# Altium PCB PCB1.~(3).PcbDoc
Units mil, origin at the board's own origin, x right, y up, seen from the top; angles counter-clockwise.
Board outline 2756 x 2756 mil, 4 copper layers (Top Layer, Internal Plane 1, Internal Plane 2, Bottom Layer), stack 18.2 mil thick; 11 components, 12 nets, 54 pads, 0 vias.
Unrouted connection lines stored in the file: 36.
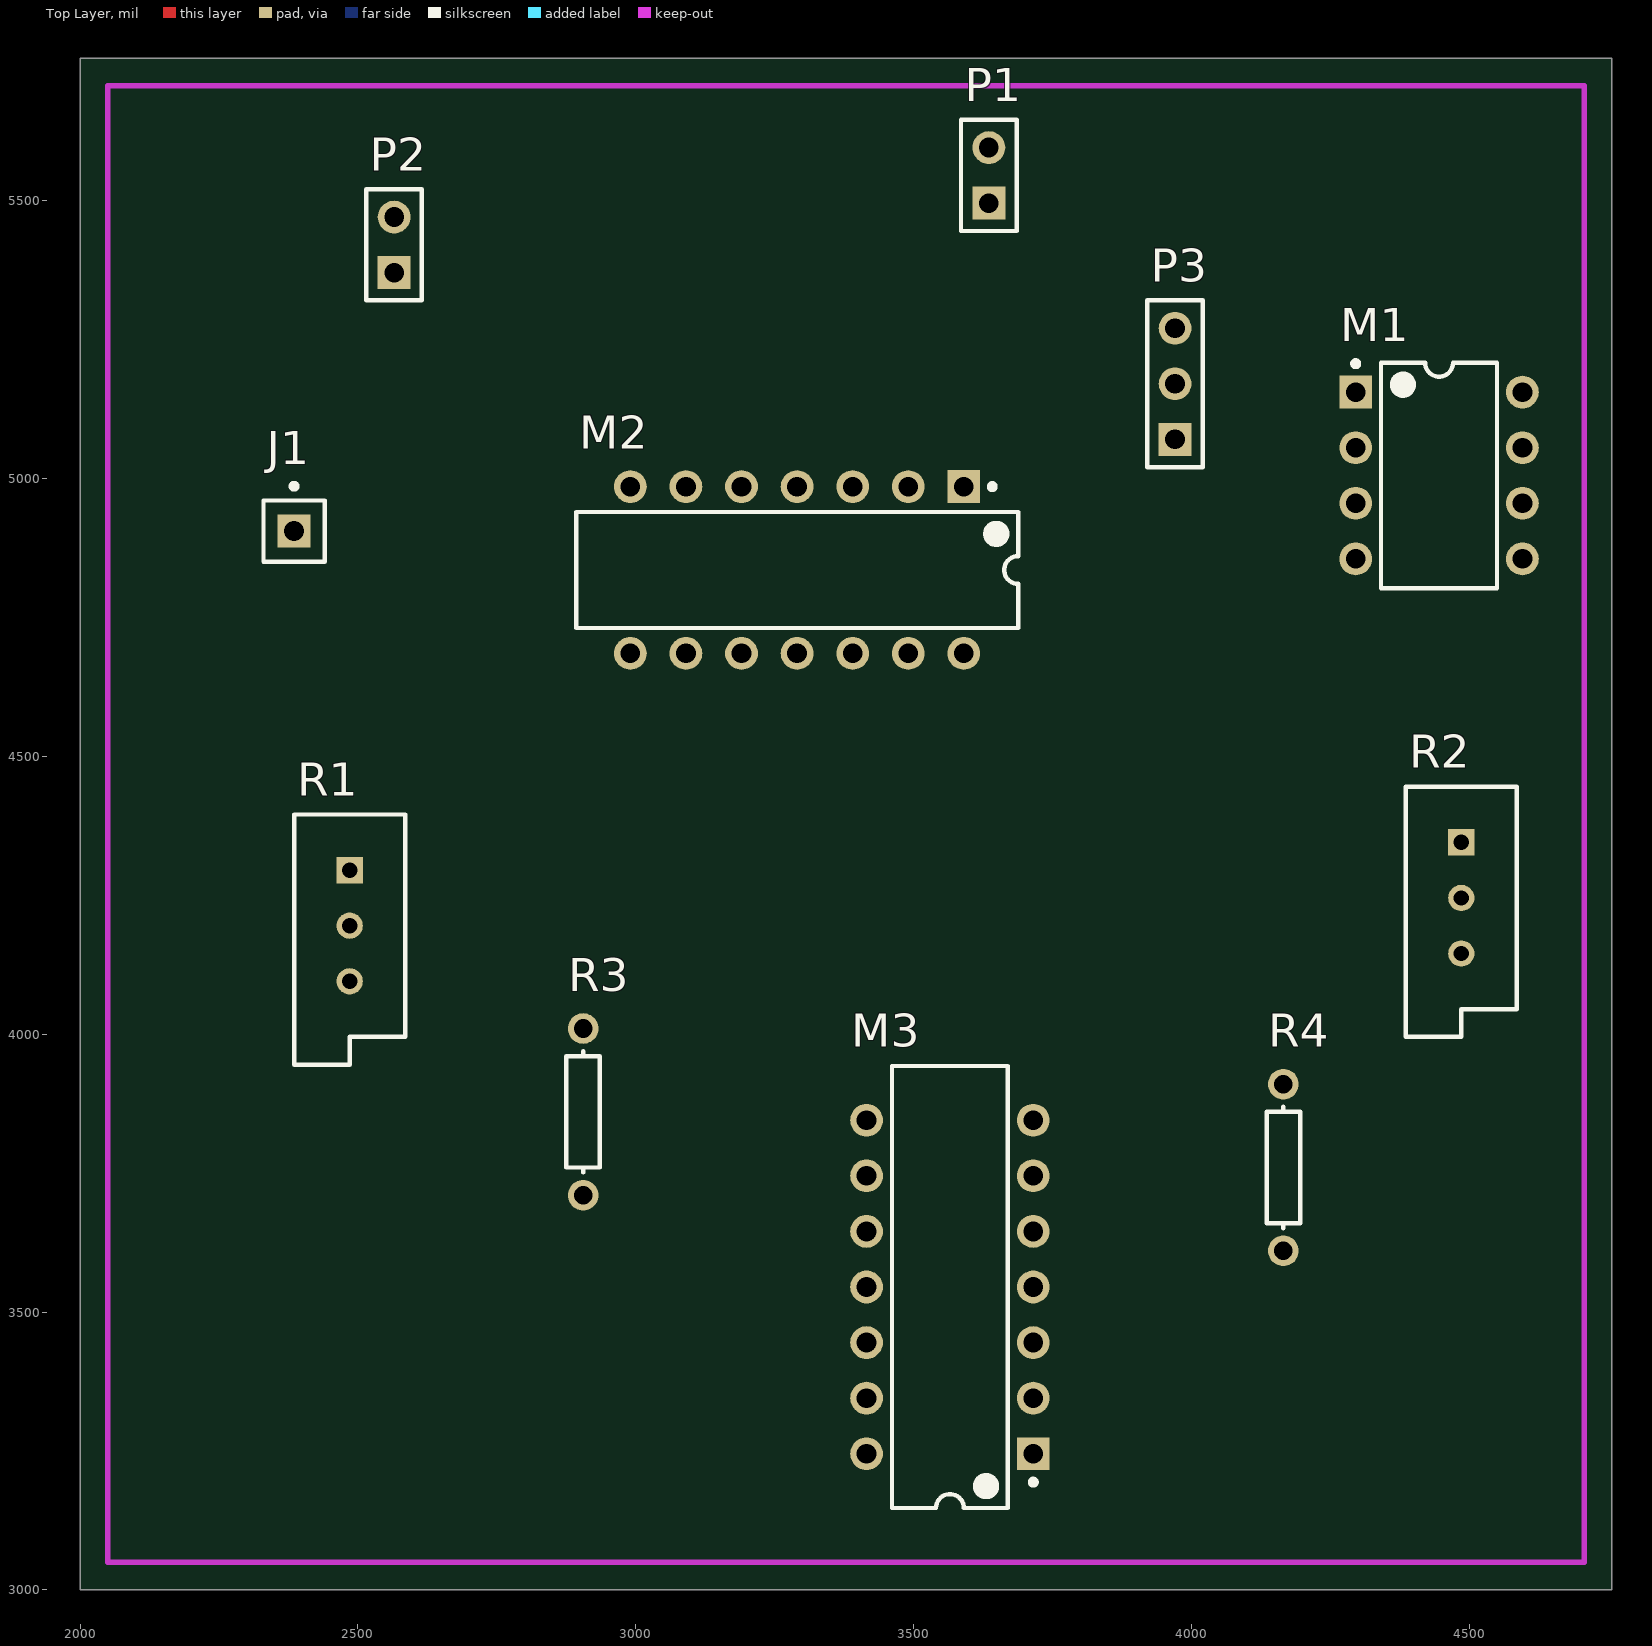
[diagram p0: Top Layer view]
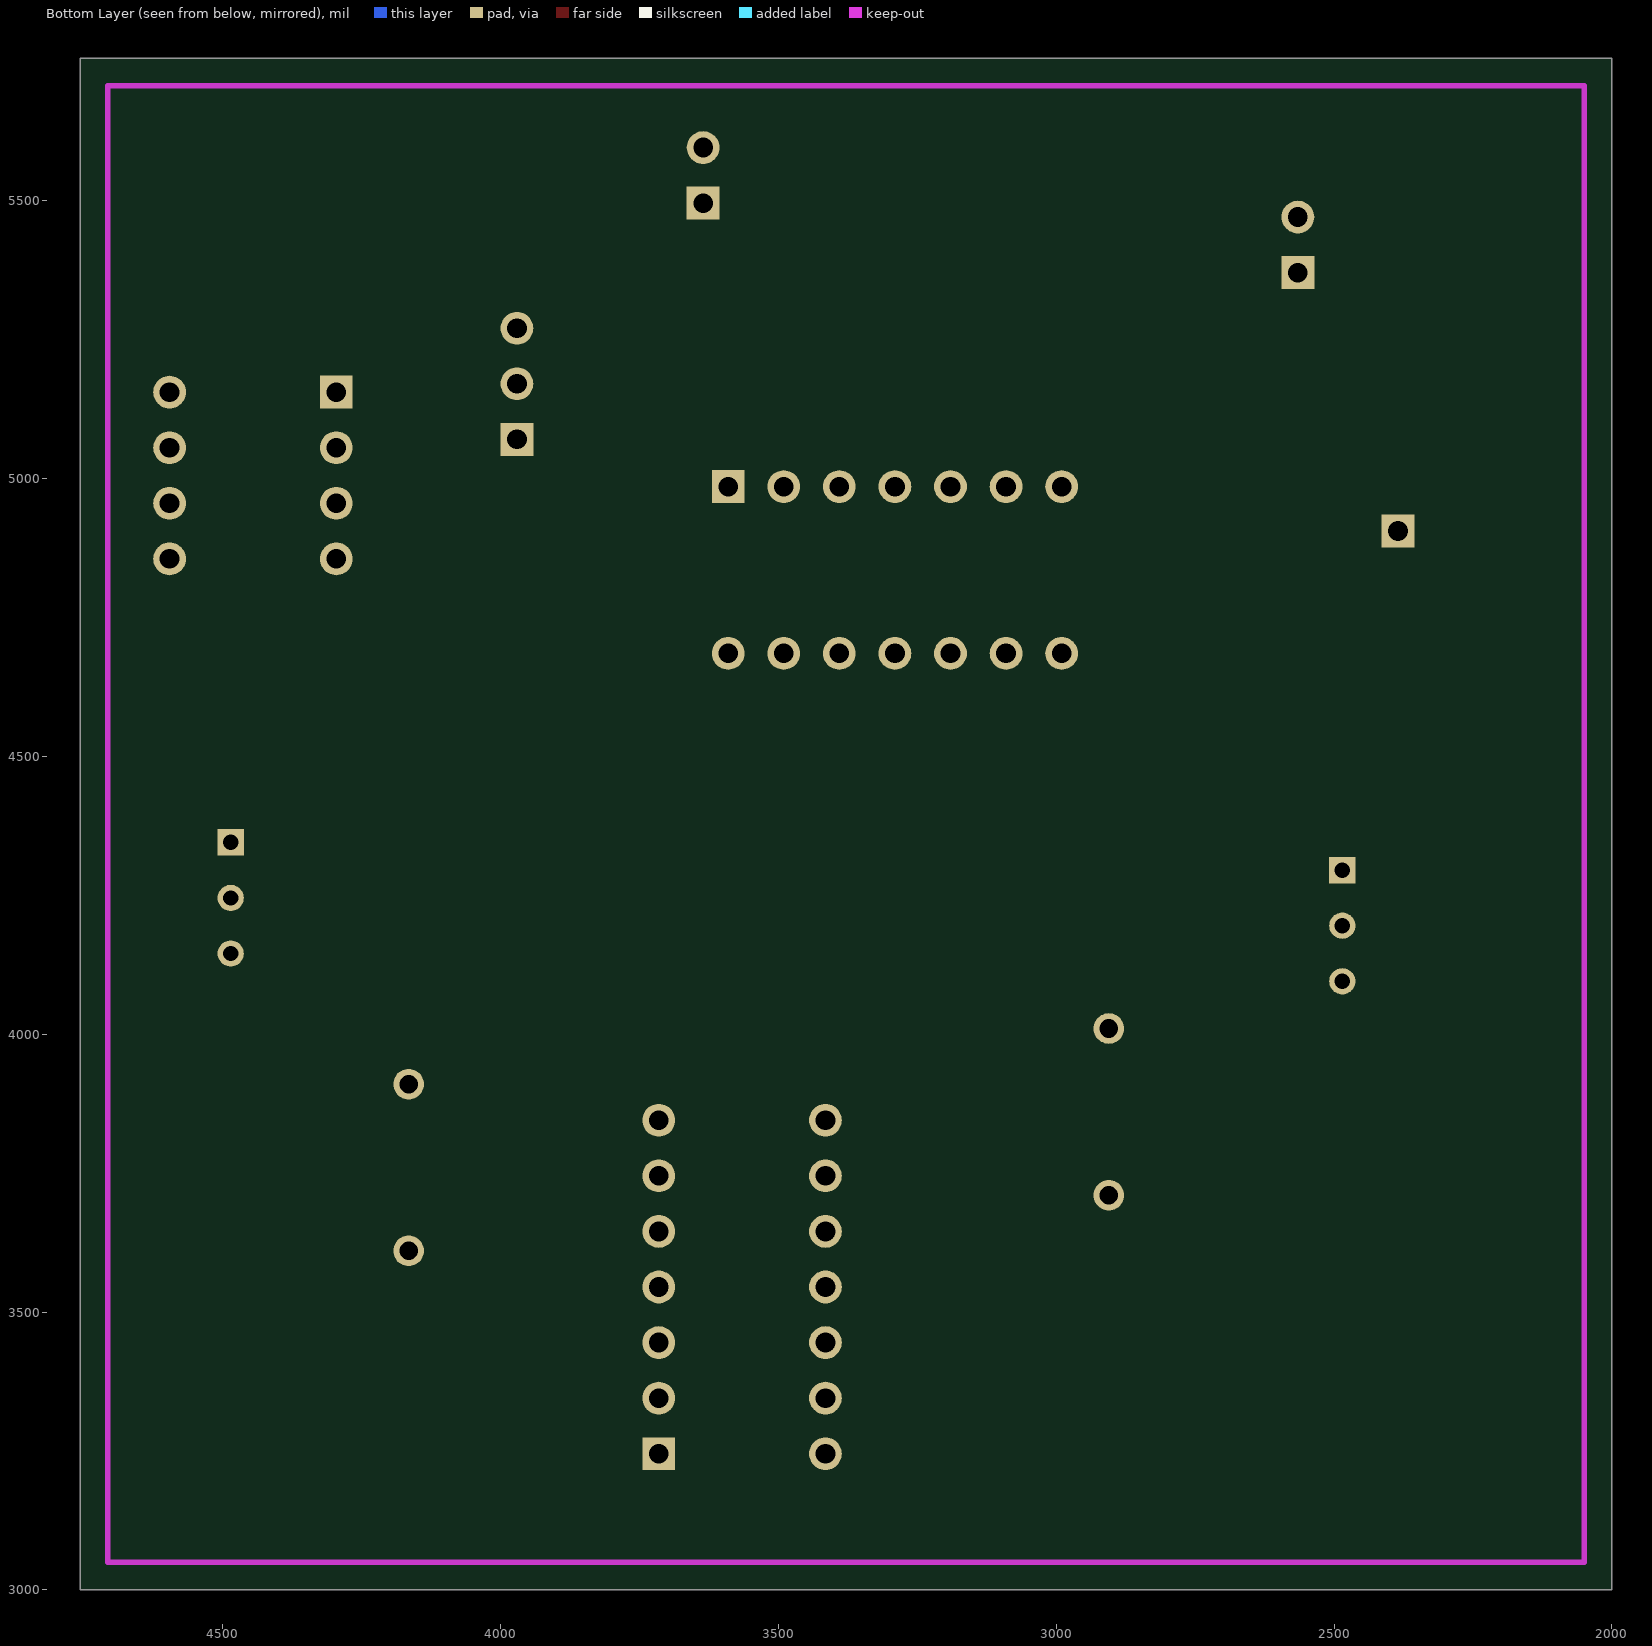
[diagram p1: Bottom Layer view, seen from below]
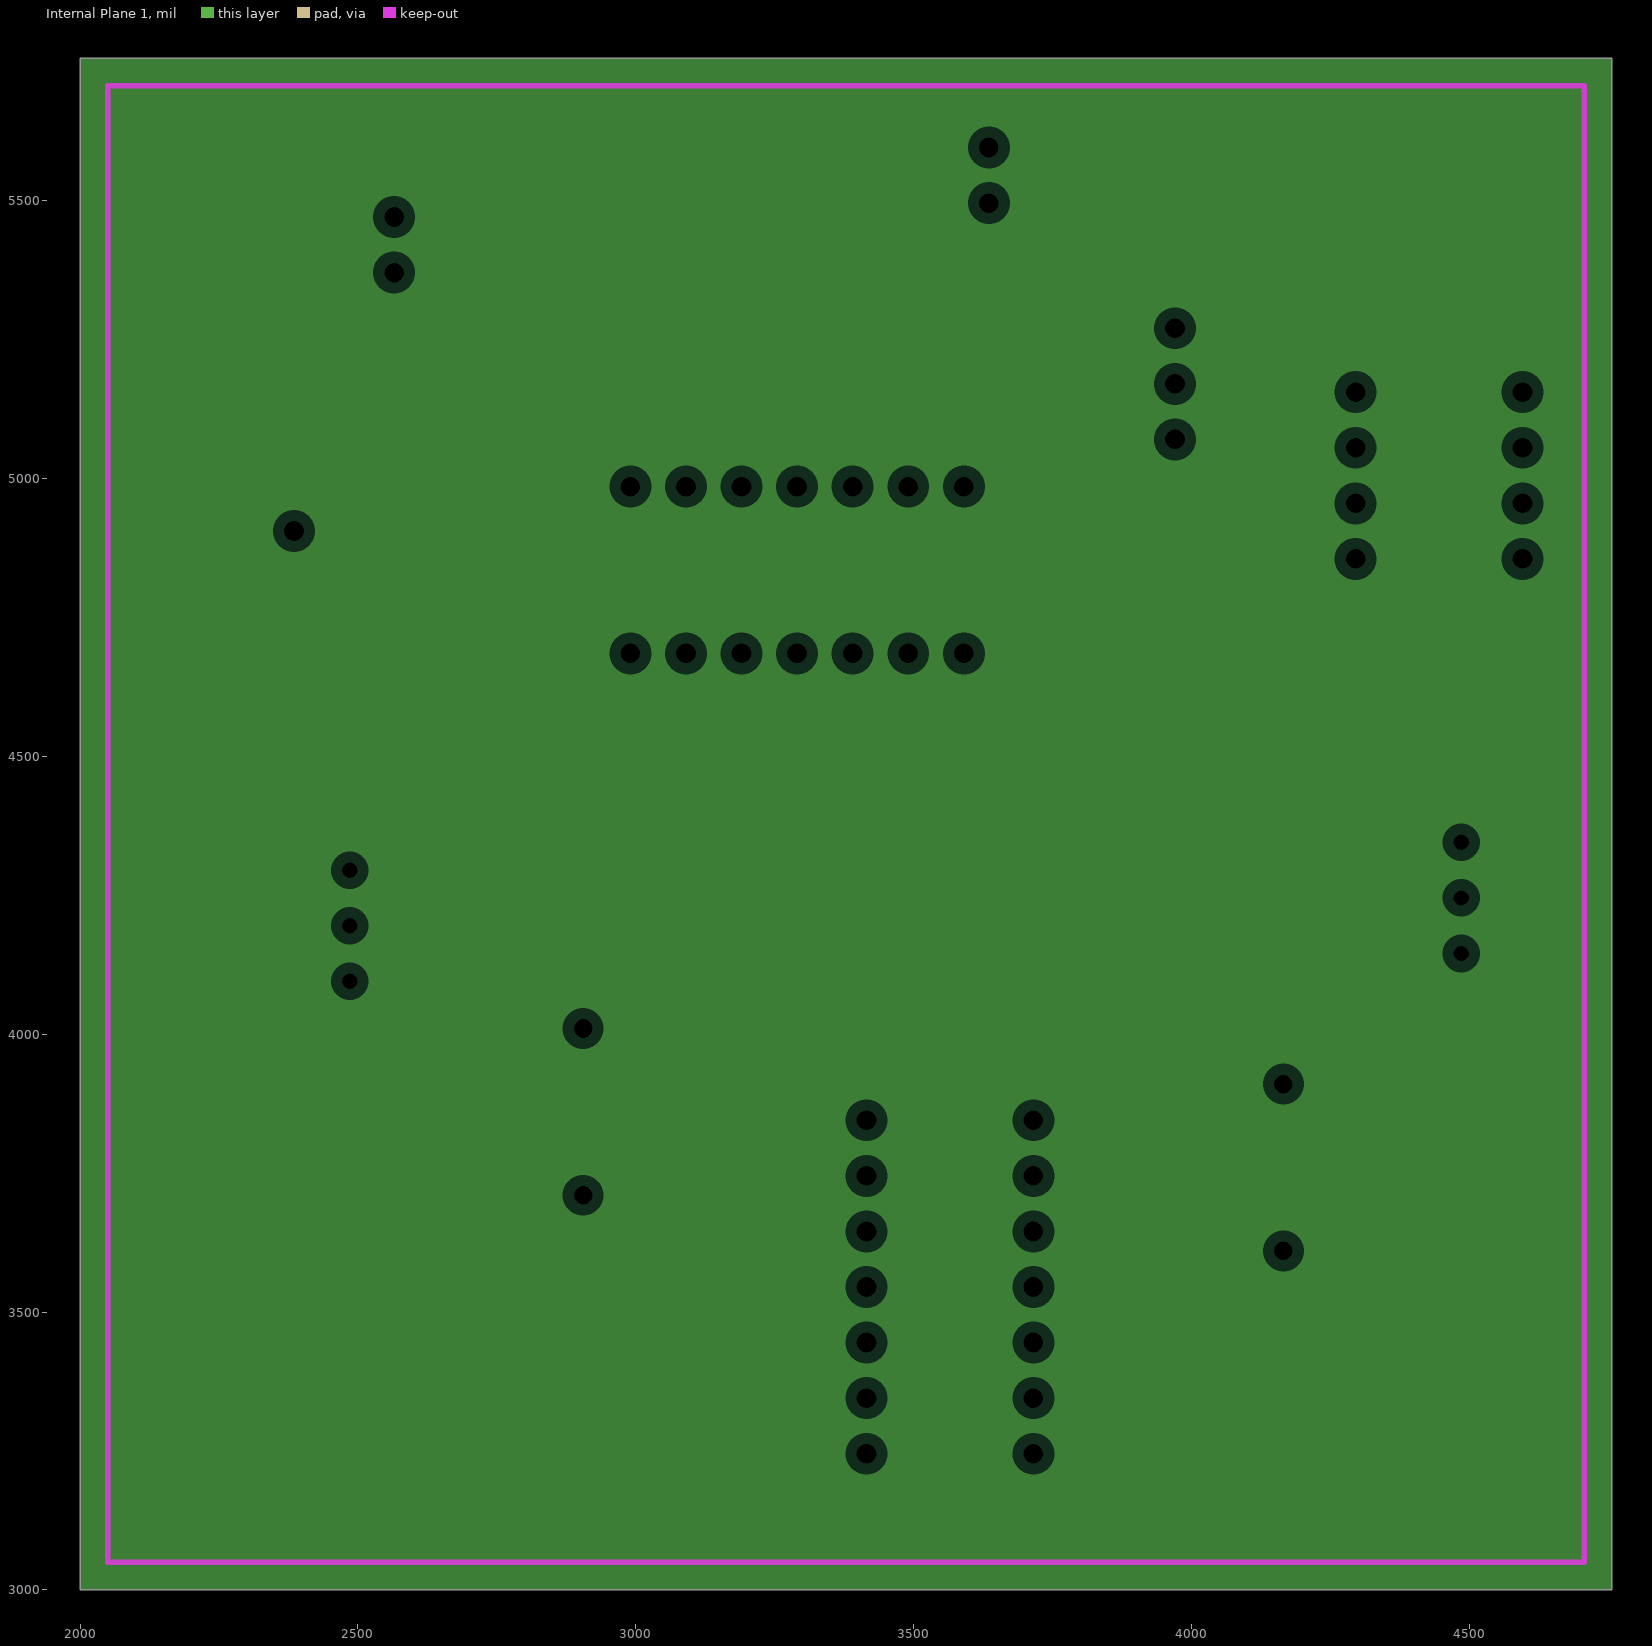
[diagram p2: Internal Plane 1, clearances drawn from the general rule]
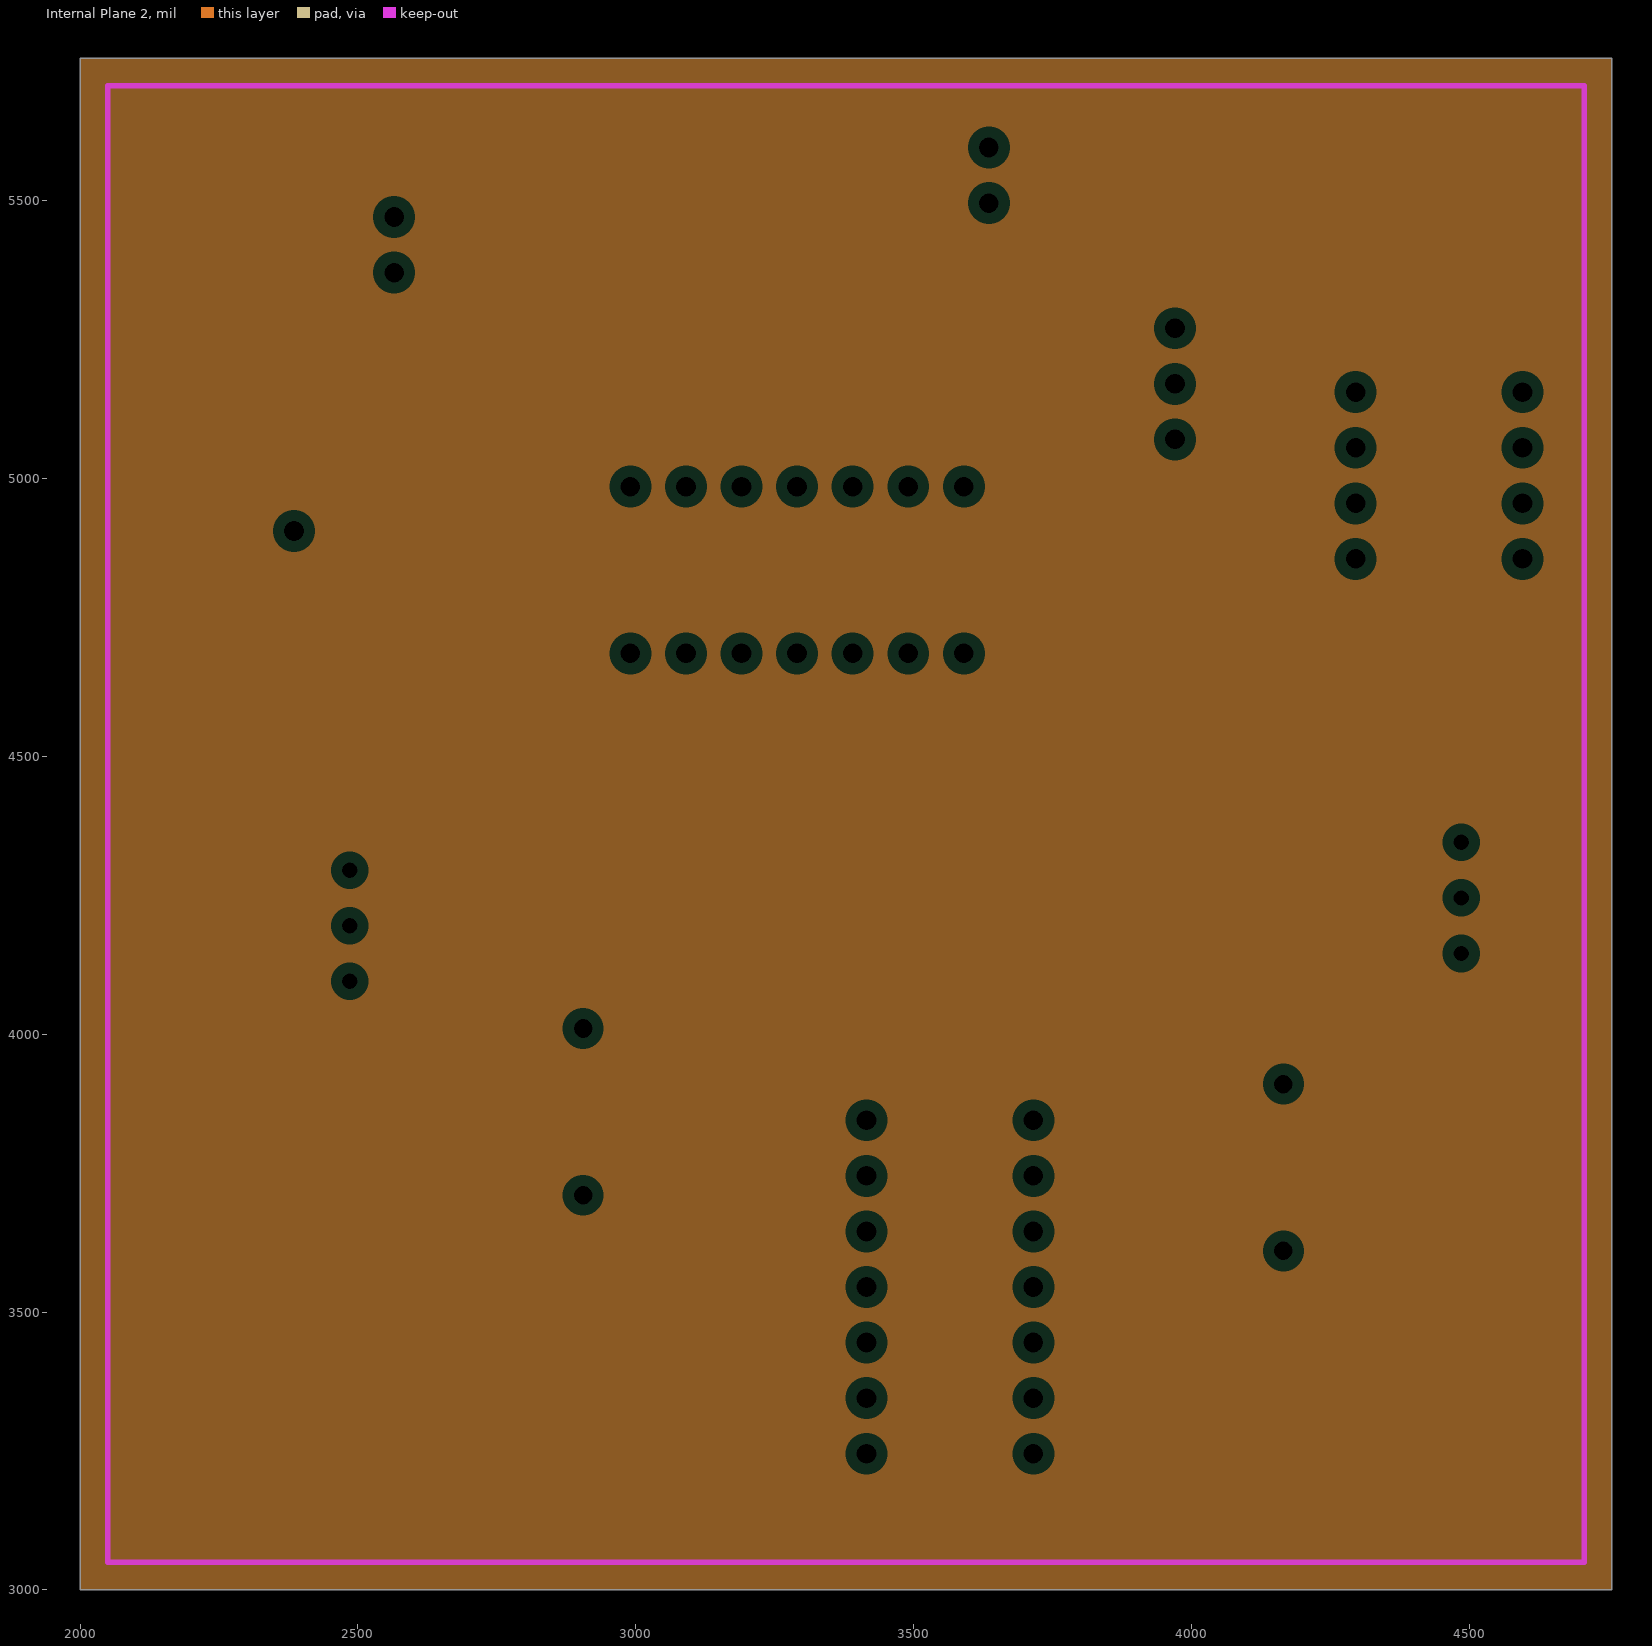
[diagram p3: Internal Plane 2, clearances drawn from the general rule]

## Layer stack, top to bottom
Top Solder: solder mask 0.4, Solder Resist, Dk 3.5
Top Layer: signal copper 1.4
Internal Plane 1: plane copper 1.4
Internal Plane 2: plane copper 1.4
Dielectric 1: dielectric 12.6, FR-4, Dk 4.8
Bottom Layer: signal copper 1.4
Bottom Solder: solder mask 0.4, Solder Resist, Dk 3.5

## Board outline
2000,3000 4756,3000 4756,5756 2000,5756

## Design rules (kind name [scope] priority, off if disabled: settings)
Clearance [All] p1: gap=30
PlaneClearance [All] p1: clearance=20
PlaneConnect [All] p1: planeconnectstyle=Relief reliefexpansion=20 reliefentries=4 reliefconductorwidth=10 reliefairgap=10
PolygonConnect [All] p1: connectstyle=Relief reliefconductorwidth=10 reliefentries=4 polygonreliefangle="90 Angle" airgapwidth=10
RoutingVias [All] p1: holewidth=32 width=62 viastyle="Through Hole" minholewidth=28 minwidth=50 maxholewidth=28 maxwidth=50
SolderMaskExpansion [All] p1: expansion=4
Width [All] p1: maxlimit=20 minlimit=20 preferedwidth=20
28 further rules are at their usual default settings.

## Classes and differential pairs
component class Proj1: J1 M1 M2 M3 P1 P2 P3 R3 R4

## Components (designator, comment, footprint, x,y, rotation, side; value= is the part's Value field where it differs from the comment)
J1 "Socket" PIN1 2385,4905 r0 top
M1 "ALD1117" DIP-8 4445,5005 r0 top
M2 "ALD1105" DIP-14 3290,4835 r270 top
M3 "ALD1106" DIP-14 3565,3545 r180 top
P1 "Header 2" HDR1X2 3635,5495 r90 top
P2 "Header 2" HDR1X2 2565,5370 r90 top
P3 "Header 3" HDR1X3 3970,5070 r90 top
R1 "RPot" VR5 2485,4195 r270 top
R2 "RPot" VR5 4485,4245 r270 top
R3 "Res1" AXIAL-0.3 2905,3860 r90 top
R4 "Res1" AXIAL-0.3 4165,3760 r90 top

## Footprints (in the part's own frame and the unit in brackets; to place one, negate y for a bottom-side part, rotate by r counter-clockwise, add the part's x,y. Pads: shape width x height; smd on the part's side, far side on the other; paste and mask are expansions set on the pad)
AXIAL-0.3 [mm] "Axial Device, Thru-Hole; 2 Leads; 0.3 in Pin Spacing"
  round 1.4 hole 0.85: 1(-3.81,0) 2(3.81,0)
  silkscreen extent -2.77,-0.76 2.77,0.76
DIP-8 [mm] "DIP, 8-Pin, Row Spacing 7.62 mm, Pitch 2.54 mm"
  rect 1.5x1.5 hole 0.9: 1(-3.81,3.81)
  round 1.5 hole 0.9: 2(-3.81,1.27) 3(-3.81,-1.27) 4(-3.81,-3.81) 5(3.81,-3.81) 6(3.81,-1.27) 7(3.81,1.27) 8(3.81,3.81)
  silkscreen extent -3.93,-5.15 2.65,5.23, body extent -3.6,-5.15 3.6,5.15, height 5.33
DIP-14 [mm] "DIP, 14-Pin, Row Spacing 7.62 mm, Pitch 2.54 mm"
  rect 1.5x1.5 hole 0.9: 1(-3.81,7.62)
  round 1.5 hole 0.9: 2(-3.81,5.08) 3(-3.81,2.54) 4(-3.81,0) 5(-3.81,-2.54) 6(-3.81,-5.08) 7(-3.81,-7.62) 8(3.81,-7.62) 9(3.81,-5.08) 10(3.81,-2.54) 11(3.81,0) 12(3.81,2.54) 13(3.81,5.08) 14(3.81,7.62)
  silkscreen extent -3.93,-10.1 2.65,10.1, body extent -3.6,-10.1 3.6,10.1, height 5.08
HDR1X2 [mm] "Connector; Header; 2 Position"
  rect 1.5x1.5 hole 0.9: 1(0,0)
  round 1.5 hole 0.9: 2(2.54,0)
  silkscreen extent -1.27,-1.27 3.81,1.27
HDR1X3 [mm] "Connector; Header; 3 Position"
  rect 1.5x1.5 hole 0.9: 1(0,0)
  round 1.5 hole 0.9: 2(2.54,0) 3(5.08,0)
  silkscreen extent -1.27,-1.27 6.35,1.27
PIN1 [mm] "Connector; Plug"
  rect 1.5x1.5 hole 0.9: 1(0,0)
  silkscreen extent -1.4,-1.4 1.4,2.17
VR5 [mm] "Thru-Hole; 3 Leads"
  rect 1.2x1.2 hole 0.7: 1(-2.54,0)
  round 1.2 hole 0.7: 2(0,0) 3(2.54,0)
  silkscreen extent -5.08,-2.54 6.35,2.54

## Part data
M1: "Dual P-channel matched MOSFET array"
M2: "Dual P-channel and dual N-channel matched MOSFET array"
M3: "Quad N-channel matched MOSFET array"
P1 P2: "Header, 2-Pin"
P3: "Header, 3-Pin"
R1 R2: "Potentiometer"
R3 R4: "Resistor"

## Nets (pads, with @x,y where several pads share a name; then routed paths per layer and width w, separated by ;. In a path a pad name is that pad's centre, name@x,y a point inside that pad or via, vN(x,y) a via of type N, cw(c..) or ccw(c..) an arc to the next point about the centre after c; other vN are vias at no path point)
GND: P1.1 P3.1
NetJ1_1: J1.1 M1.2 M2.5 M2.14
NETLABEL5: M2.6
NETLABEL9: M1.3 M1.5 M1.6 M1.7 M1.8 M2.3 M2.4 M2.12 R1.1 R1.2 R2.1 R2.2
NetM1_1: M1.1 M3.1 P1.2
NetM2_1: M2.1 M2.2 M2.10 M2.13
NetM2_7: M2.7 M2.8 M2.11 M3.10
NetM3_2: M3.2 M3.5 M3.6 R4.1
NetM3_3: M3.3 M3.4 M3.7 M3.8 M3.12 P3.3
NetM3_9: M3.9 M3.13 M3.14 R3.1
NetR1_3: R1.3 R3.2
NetR2_3: R2.3 R4.2
pads on no net: M1.4 M2.9 M3.11 P2.1 P2.2 P3.2

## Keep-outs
Keep-Out Layer:
  lines w10: 2050,3050 2050,5706 4706,5706 4706,3050 2050,3050

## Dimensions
2050,3050 to 2050,5706 on Mechanical 1
2050,3050 to 4706,3050 on Mechanical 1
